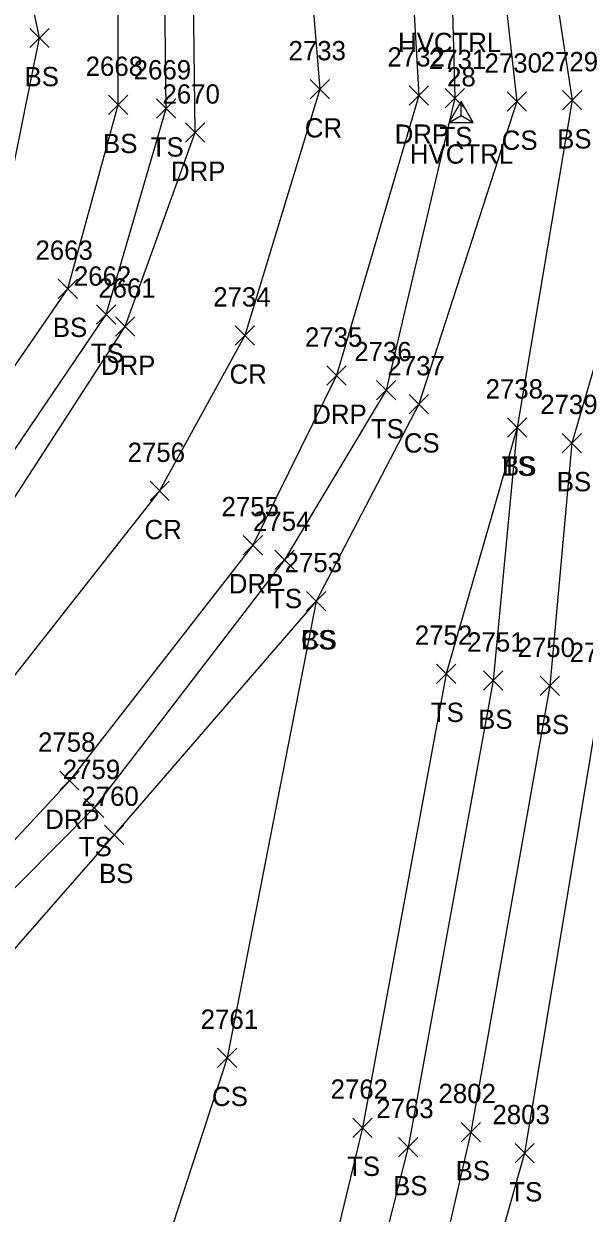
# Model space of a CAD drawing. Extents: x 1472233 to 1475777, y 540726 to 543442.
# Drawn here: x 1474117.3 to 1474175.4, y 542676.8 to 542800 of the extents above; entities that cross this region are included whole.
import ezdxf

# ---------------------------------------------------------------- set-up
doc = ezdxf.new("R2010")
doc.units = 0
for name, color, linetype in [('C_A', 7, 'Continuous'), ('C_I', 7, 'Continuous'), ('CPSM', 7, 'Continuous'), ('L_A', 7, 'Continuous'), ('L_I', 7, 'Continuous'), ('L_TIC', 7, 'Continuous'), ('LELB', 7, 'Continuous'), ('P_A', 7, 'Continuous'), ('P_I', 7, 'Continuous'), ('P_TIC', 7, 'Continuous'), ('PRC', 7, 'Continuous'), ('R_A', 7, 'Continuous'), ('R_I', 7, 'Continuous'), ('R_TIC', 7, 'Continuous'), ('RDP', 7, 'Continuous')]:
    doc.layers.add(name, color=color, linetype=linetype)

msp = doc.modelspace()

# ---------------------------------------------------------------- linework, layer by layer
at = {"layer": 'CPSM'}
for p, q in [((1474161.38, 542789.77), (1474162.63, 542791.94)), ((1474163.88, 542789.77), (1474162.63, 542791.94)), ((1474162.63, 542790.49), (1474162.63, 542791.94)), ((1474161.38, 542789.77), (1474162.63, 542790.49)), ((1474161.38, 542789.77), (1474163.88, 542789.77)), ((1474162.63, 542790.49), (1474162.63, 542790.49)), ((1474162.63, 542790.49), (1474163.88, 542789.77))]:
    msp.add_line(p, q, dxfattribs=at)
at = {"layer": 'L_TIC'}
for points in [[(1474117.95, 542797.51), (1474119.95, 542799.51)], [(1474119.95, 542797.51), (1474117.95, 542799.51)], [(1474126.08, 542790.58), (1474128.08, 542792.58)], [(1474128.08, 542790.58), (1474126.08, 542792.58)], [(1474131.06, 542790.22), (1474133.06, 542792.22)], [(1474133.06, 542790.22), (1474131.06, 542792.22)], [(1474160.97, 542791.29), (1474162.97, 542793.29)], [(1474162.97, 542791.29), (1474160.97, 542793.29)], [(1474167.39, 542790.92), (1474169.39, 542792.92)], [(1474169.39, 542790.92), (1474167.39, 542792.92)], [(1474173.14, 542791.06), (1474175.14, 542793.06)], [(1474175.14, 542791.06), (1474173.14, 542793.06)], [(1474120.88, 542771.53), (1474122.88, 542773.53)], [(1474122.88, 542771.53), (1474120.88, 542773.53)], [(1474124.85, 542768.85), (1474126.85, 542770.85)], [(1474126.85, 542768.85), (1474124.85, 542770.85)], [(1474153.87, 542761.03), (1474155.87, 542763.03)], [(1474155.87, 542761.03), (1474153.87, 542763.03)], [(1474157.25, 542759.56), (1474159.25, 542761.56)], [(1474159.25, 542759.56), (1474157.25, 542761.56)], [(1474167.42, 542757.16), (1474169.42, 542759.16)], [(1474169.42, 542757.16), (1474167.42, 542759.16)], [(1474167.42, 542757.16), (1474169.42, 542759.16)], [(1474169.42, 542757.16), (1474167.42, 542759.16)], [(1474173.09, 542755.55), (1474175.09, 542757.55)], [(1474175.09, 542755.55), (1474173.09, 542757.55)], [(1474143.32, 542743.44), (1474145.32, 542745.44)], [(1474145.32, 542743.44), (1474143.32, 542745.44)], [(1474146.6, 542739.17), (1474148.6, 542741.17)], [(1474148.6, 542739.17), (1474146.6, 542741.17)], [(1474146.6, 542739.17), (1474148.6, 542741.17)], [(1474148.6, 542739.17), (1474146.6, 542741.17)], [(1474160.08, 542731.65), (1474162.08, 542733.65)], [(1474162.08, 542731.65), (1474160.08, 542733.65)], [(1474164.95, 542730.94), (1474166.95, 542732.94)], [(1474166.95, 542730.94), (1474164.95, 542732.94)], [(1474164.95, 542730.94), (1474166.95, 542732.94)], [(1474166.95, 542730.94), (1474164.95, 542732.94)], [(1474170.82, 542730.38), (1474172.82, 542732.38)], [(1474172.82, 542730.38), (1474170.82, 542732.38)], [(1474123.61, 542717.74), (1474125.61, 542719.74)], [(1474125.61, 542717.74), (1474123.61, 542719.74)], [(1474125.67, 542714.96), (1474127.67, 542716.96)], [(1474127.67, 542714.96), (1474125.67, 542716.96)], [(1474137.38, 542691.86), (1474139.38, 542693.86)], [(1474139.38, 542691.86), (1474137.38, 542693.86)], [(1474151.4, 542684.62), (1474153.4, 542686.62)], [(1474153.4, 542684.62), (1474151.4, 542686.62)], [(1474162.62, 542684.17), (1474164.62, 542686.17)], [(1474164.62, 542684.17), (1474162.62, 542686.17)], [(1474156.14, 542682.61), (1474158.14, 542684.61)], [(1474158.14, 542682.61), (1474156.14, 542684.61)], [(1474168.21, 542681.98), (1474170.21, 542683.98)], [(1474170.21, 542681.98), (1474168.21, 542683.98)]]:
    msp.add_lwpolyline(points, dxfattribs=at)
at = {"layer": 'LELB'}
for points in [[(1474164.82, 542884.74), (1474177.08, 542859.64), (1474183.9, 542820.79), (1474184.96, 542792.13), (1474179.18, 542755.14), (1474177.15, 542730.87), (1474169.21, 542682.98), (1474159.78, 542649.64), (1474154.97, 542620.04), (1474135.25, 542580.36), (1474109.96, 542543.28), (1474096.67, 542524.43), (1474067.27, 542494.3), (1474046, 542463.55), (1474027.35, 542441.47), (1474014.9, 542415.95), (1474008.61, 542382.85), (1474022.04, 542371.96), (1474043.45, 542321.48), (1474074.48, 542289.92), (1474118.03, 542249.87), (1474148.2, 542220.42), (1474162.9, 542206.56)], [(1474149.71, 542878.61), (1474164.65, 542855.05), (1474170.16, 542818.01), (1474174.14, 542792.06), (1474168.42, 542758.16), (1474165.95, 542731.94)], [(1474018.03, 542683.18), (1474027.63, 542686.83), (1474054.62, 542691.03), (1474070.79, 542705.62), (1474092.99, 542726.88), (1474111.59, 542748.82), (1474125.85, 542769.85), (1474132.06, 542791.22), (1474131.8, 542814.84), (1474116.48, 542854.31), (1474111.7, 542860.51)], [(1474027.63, 542686.83), (1474051.42, 542695.82), (1474068.24, 542708.41), (1474089.98, 542730.51), (1474107.93, 542752.29), (1474121.88, 542772.53), (1474127.08, 542791.58), (1474127.12, 542813.94), (1474113.55, 542845.74), (1474102.69, 542855.23)], [(1474164.65, 542855.05), (1474165.52, 542817.42), (1474168.39, 542791.92), (1474158.25, 542760.56), (1474147.6, 542740.17), (1474138.38, 542692.86), (1474125.13, 542652.19)], [(1474045.33, 542700.24), (1474063.13, 542714.75), (1474083.41, 542736.12), (1474100.45, 542758.09), (1474114.5, 542776.6), (1474118.95, 542798.51), (1474116.01, 542812.59), (1474102.38, 542835.59), (1474091.33, 542848.77)], [(1474178.93, 542819.53), (1474183.85, 542789.78), (1474174.09, 542756.55), (1474171.82, 542731.38), (1474163.62, 542685.17), (1474155.6, 542650.09), (1474149.2, 542621.33), (1474131.46, 542582.13), (1474106.27, 542545.45), (1474094.34, 542527.6), (1474062.74, 542495.35), (1474043.24, 542465.87), (1474022.83, 542445.04)], [(1474161.33, 542816.84), (1474161.97, 542792.29), (1474154.87, 542762.03), (1474144.32, 542744.44), (1474124.61, 542718.74), (1474101.99, 542695.96), (1474093.47, 542686.46), (1474089.24, 542682.58), (1474080.19, 542673.18), (1474075.15, 542661.11), (1474077.15, 542641.54), (1474095.47, 542632.72), (1474116.89, 542615.57), (1474111.23, 542585.69), (1474090.52, 542556.35), (1474073.67, 542551.32), (1474038.07, 542519.87), (1474011.53, 542544.93), (1473997.92, 542550.92)], [(1474168.42, 542758.16), (1474161.08, 542732.65), (1474152.4, 542685.62), (1474143.99, 542650.7), (1474139.21, 542638.25), (1474125.13, 542652.19), (1474113.17, 542670.76), (1474108, 542694.64)], [(1474147.6, 542740.17), (1474126.67, 542715.96), (1474108, 542694.64), (1474101.39, 542688.23), (1474093.16, 542677.96), (1474090.14, 542675.56), (1474083.3, 542668.09), (1474080.25, 542657.73), (1474086.54, 542649.05), (1474102.87, 542638.26), (1474116.97, 542621), (1474129.54, 542610.53)], [(1474165.95, 542731.94), (1474157.14, 542683.61), (1474148.57, 542649.89), (1474143.29, 542635.5), (1474139.19, 542631.93), (1474131.36, 542636.12), (1474120.53, 542648.69), (1474108.56, 542670.06), (1474101.39, 542688.23), (1474095.89, 542684.64), (1474093.95, 542684.48), (1474093.45, 542683.67), (1474093.16, 542677.96), (1474112.56, 542649.15), (1474130.63, 542628.83), (1474135.77, 542616.46), (1474134.45, 542606.68), (1474129.24, 542593.89), (1474099.76, 542548.63), (1474087.76, 542535.06), (1474054.57, 542501.68), (1474028.74, 542469.85), (1474011.69, 542457.24), (1473991.56, 542429.6)]]:
    msp.add_lwpolyline(points, dxfattribs=at)
at = {"layer": 'P_TIC'}
for points in [[(1474146.99, 542792.2), (1474148.99, 542794.2)], [(1474148.99, 542792.2), (1474146.99, 542794.2)], [(1474139.2, 542766.69), (1474141.2, 542768.69)], [(1474141.2, 542766.69), (1474139.2, 542768.69)], [(1474130.39, 542750.59), (1474132.39, 542752.59)], [(1474132.39, 542750.59), (1474130.39, 542752.59)]]:
    msp.add_lwpolyline(points, dxfattribs=at)
at = {"layer": 'PRC'}
msp.add_lwpolyline([(1474124.73, 542867.45), (1474138.24, 542842.57), (1474146.26, 542814.27), (1474147.99, 542793.2), (1474140.2, 542767.69), (1474131.39, 542751.59), (1474113.96, 542729.51), (1474092.05, 542706.63), (1474043.97, 542656.44), (1473995.22, 542610.58), (1473969.45, 542582.1), (1473923.18, 542533.15), (1473898.02, 542503.68), (1473870.62, 542473.58), (1473851.91, 542452.04)], dxfattribs=at)
at = {"layer": 'R_TIC'}
for points in [[(1474157.25, 542791.55), (1474159.25, 542793.55)], [(1474159.25, 542791.55), (1474157.25, 542793.55)], [(1474134.07, 542787.71), (1474136.07, 542789.71)], [(1474136.07, 542787.71), (1474134.07, 542789.71)], [(1474126.81, 542767.61), (1474128.81, 542769.61)], [(1474128.81, 542767.61), (1474126.81, 542769.61)], [(1474148.71, 542762.53), (1474150.71, 542764.53)], [(1474150.71, 542762.53), (1474148.71, 542764.53)], [(1474140.06, 542744.97), (1474142.06, 542746.97)], [(1474142.06, 542744.97), (1474140.06, 542746.97)], [(1474121.05, 542720.57), (1474123.05, 542722.57)], [(1474123.05, 542720.57), (1474121.05, 542722.57)]]:
    msp.add_lwpolyline(points, dxfattribs=at)
at = {"layer": 'RDP'}
for points in [[(1473999.37, 542698.9), (1474012.85, 542687.03), (1474018.03, 542683.18), (1474032.84, 542680.35), (1474045.66, 542682.34), (1474058.91, 542689.51), (1474072.96, 542703.6), (1474094.08, 542724.98), (1474113.77, 542746.94), (1474127.81, 542768.61), (1474135.07, 542788.71), (1474134.76, 542814.36), (1474118.74, 542856.08), (1474114.45, 542861.9)], [(1474156.9, 542816.07), (1474158.25, 542792.55), (1474149.71, 542763.53), (1474141.06, 542745.97), (1474122.05, 542721.57), (1474099.16, 542696.92), (1474072.3, 542669.38), (1474064.97, 542659.15), (1474064.16, 542645.99), (1474070.96, 542633.45), (1474104.89, 542594.5), (1474067.57, 542556.96), (1474038.11, 542526.02), (1474001.11, 542557.22), (1473988.17, 542557.88), (1473978.19, 542554.56), (1473968.9, 542548.06), (1473950.18, 542529.64), (1473913.19, 542491.65), (1473890.53, 542466.06), (1473881.45, 542451.89), (1473878.79, 542441.67), (1473879.57, 542429.36), (1473882.06, 542422.12)]]:
    msp.add_lwpolyline(points, dxfattribs=at)

# ---------------------------------------------------------------- texts
at = {"layer": 'C_A'}
for p in [(1474156.09, 542797.05), (1474157.32, 542785.49)]:
    msp.add_text('HVCTRL', height=2, dxfattribs=at).set_placement(p)
at = {"layer": 'C_I'}
msp.add_text('28', height=2, dxfattribs=at).set_placement((1474161.17, 542793.49))
at = {"layer": 'L_A'}
for s, p in [('BS', (1474117.39, 542793.51)), ('BS', (1474125.52, 542786.58)), ('TS', (1474160.38, 542787.29)), ('CS', (1474166.84, 542786.92)), ('BS', (1474172.58, 542787.06)), ('TS', (1474130.47, 542786.22)), ('BS', (1474120.32, 542767.53)), ('TS', (1474124.26, 542764.85)), ('TS', (1474153.28, 542757.03)), ('CS', (1474156.69, 542755.56)), ('TS', (1474166.83, 542753.16)), ('BS', (1474166.86, 542753.16)), ('BS', (1474172.53, 542751.55)), ('TS', (1474142.73, 542739.44)), ('CS', (1474146.04, 542735.17)), ('BS', (1474146.04, 542735.17)), ('TS', (1474159.49, 542727.65)), ('BS', (1474164.39, 542726.94)), ('BS', (1474164.39, 542726.94)), ('BS', (1474170.26, 542726.38)), ('TS', (1474123.02, 542713.74)), ('BS', (1474125.11, 542710.96)), ('CS', (1474136.82, 542687.86)), ('TS', (1474150.81, 542680.62)), ('BS', (1474162.06, 542680.17)), ('BS', (1474155.58, 542678.61)), ('TS', (1474167.62, 542677.98))]:
    msp.add_text(s, height=2, dxfattribs=at).set_placement(p)
at = {"layer": 'L_I'}
for s, p in [('2731', (1474159.28, 542795.29)), ('2729', (1474170.87, 542795.06)), ('2668', (1474123.72, 542794.58)), ('2669', (1474128.7, 542794.22)), ('2730', (1474165.05, 542794.92)), ('2663', (1474118.52, 542775.53)), ('2662', (1474122.5, 542772.85)), ('2736', (1474151.55, 542765.03)), ('2737', (1474154.99, 542763.56)), ('2738', (1474165.16, 542761.16)), ('2738', (1474165.16, 542761.16)), ('2739', (1474170.82, 542759.55)), ('2754', (1474141.06, 542747.44)), ('2753', (1474144.34, 542743.17)), ('2753', (1474144.34, 542743.17)), ('2752', (1474157.83, 542735.65)), ('2751', (1474163.25, 542734.94)), ('2751', (1474163.25, 542734.94)), ('2750', (1474168.47, 542734.38)), ('2749', (1474173.88, 542733.87)), ('2759', (1474121.35, 542721.74)), ('2760', (1474123.28, 542718.96)), ('2761', (1474135.64, 542695.86)), ('2762', (1474149.1, 542688.62)), ('2802', (1474160.28, 542688.17)), ('2763', (1474153.83, 542686.61)), ('2803', (1474165.87, 542685.98))]:
    msp.add_text(s, height=2, dxfattribs=at).set_placement(p)
at = {"layer": 'P_A'}
for p in [(1474146.43, 542788.2), (1474138.63, 542762.69), (1474129.82, 542746.59)]:
    msp.add_text('CR', height=2, dxfattribs=at).set_placement(p)
at = {"layer": 'P_I'}
for s, p in [('2733', (1474144.74, 542796.2)), ('2734', (1474136.94, 542770.69)), ('2756', (1474128.07, 542754.59))]:
    msp.add_text(s, height=2, dxfattribs=at).set_placement(p)
at = {"layer": 'R_A'}
for p in [(1474155.74, 542787.55), (1474132.56, 542783.71), (1474125.3, 542763.61), (1474147.2, 542758.53), (1474138.55, 542740.97), (1474119.53, 542716.57)]:
    msp.add_text('DRP', height=2, dxfattribs=at).set_placement(p)
at = {"layer": 'R_I'}
for s, p in [('2732', (1474154.99, 542795.55)), ('2670', (1474131.68, 542791.71)), ('2661', (1474125.03, 542771.61)), ('2735', (1474146.45, 542766.53)), ('2755', (1474137.8, 542748.97)), ('2758', (1474118.79, 542724.57))]:
    msp.add_text(s, height=2, dxfattribs=at).set_placement(p)

doc.saveas('drawing.dxf')
